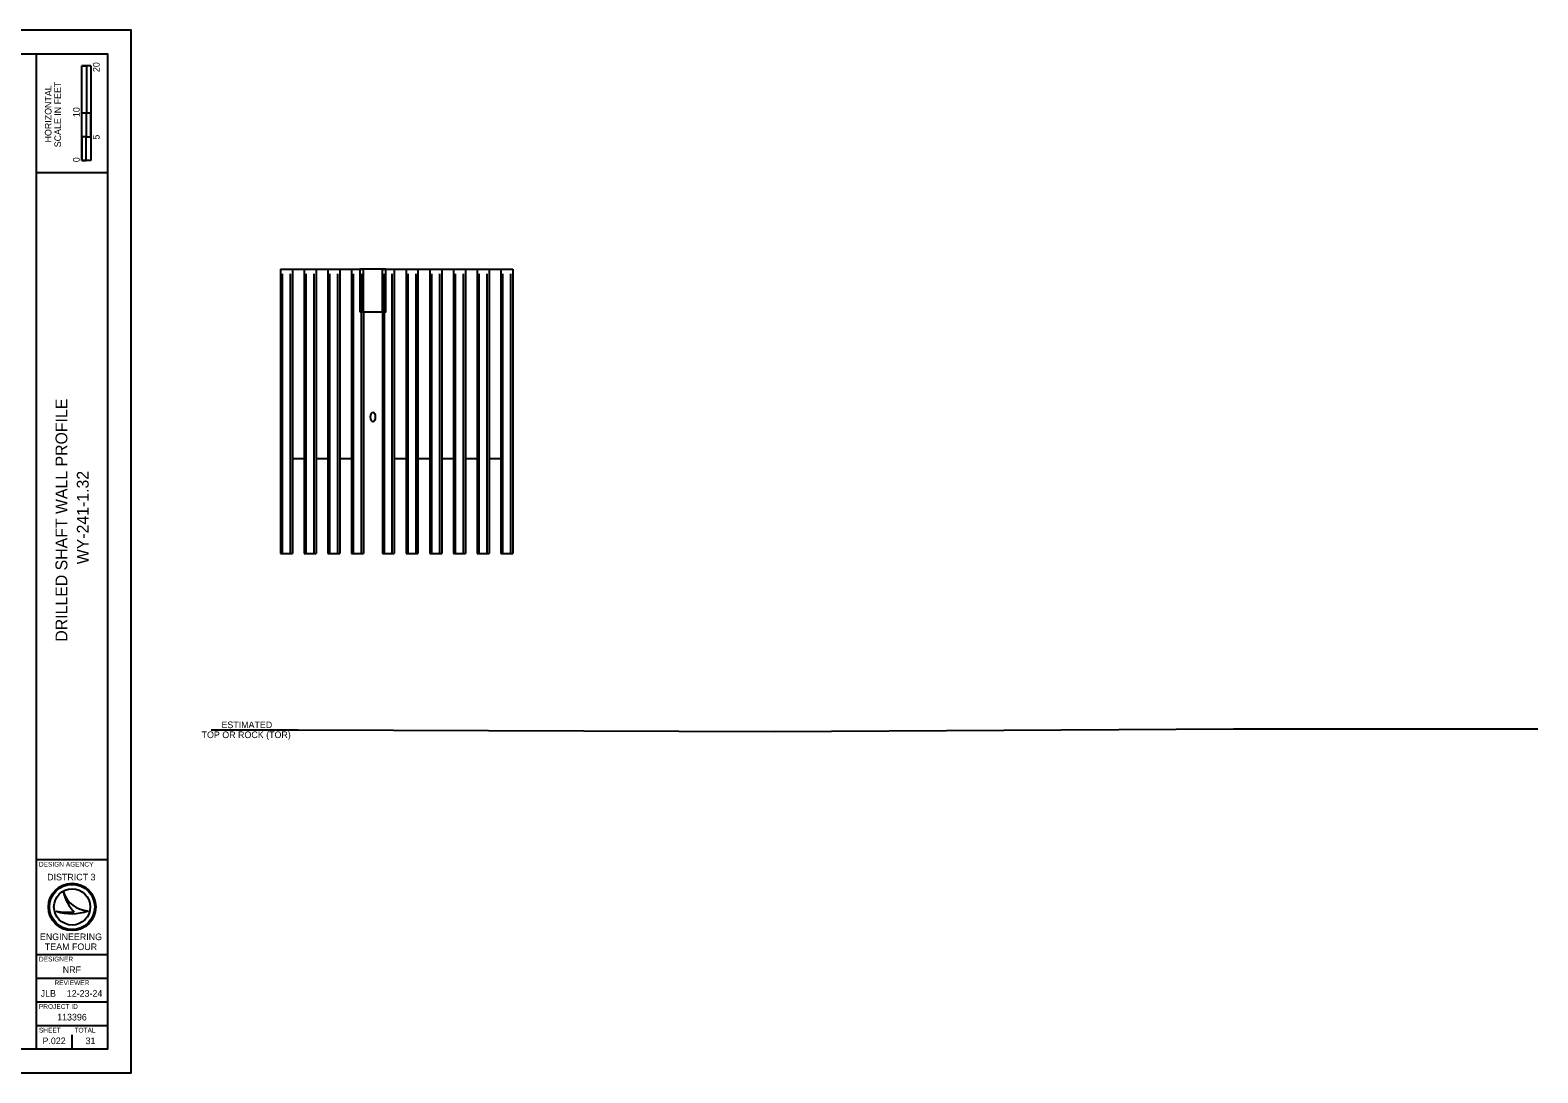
# Model space of a CAD drawing. Extents: x -276 to 637, y 1 to 221.
# Drawn here: x 319.2 to 637.4, y 0.6 to 220.6 of the extents above; entities that cross this region are included whole.
import ezdxf

# ---------------------------------------------------------------- set-up
doc = ezdxf.new("R2010")
doc.units = 0
for name, color, linetype in [('BR_P_Beam_Reinforcing', 7, 'Continuous'), ('DR_X_Culvert', 7, 'Continuous'), ('RD_P_Wall', 7, 'Continuous'), ('RD_X_Bedrock', 7, 'Continuous'), ('SH_Border', 7, 'Continuous'), ('SH_Cut_Line', 7, 'Continuous'), ('SH_Data', 7, 'Continuous')]:
    doc.layers.add(name, color=color, linetype=linetype)

msp = doc.modelspace()

# ---------------------------------------------------------------- linework, layer by layer
at = {"layer": 'BR_P_Beam_Reinforcing'}
for p, q in [((372.51, 110.18), (372.51, 169.18)), ((374.18, 110.18), (374.18, 169.18)), ((377.51, 110.18), (377.51, 169.18)), ((379.18, 110.18), (379.18, 169.18)), ((382.51, 110.18), (382.51, 169.18)), ((384.18, 110.18), (384.18, 169.18)), ((387.51, 110.18), (387.51, 169.18)), ((389.18, 161.18), (389.18, 169.18)), ((394.01, 161.18), (394.01, 169.18)), ((395.68, 110.18), (395.68, 169.18)), ((399.01, 110.18), (399.01, 169.18)), ((400.68, 110.18), (400.68, 169.18)), ((404.03, 110.18), (404.03, 169.18)), ((405.7, 110.18), (405.7, 169.18)), ((409.03, 110.18), (409.03, 169.18)), ((410.7, 110.18), (410.7, 169.18)), ((414.03, 110.18), (414.03, 169.18)), ((415.7, 110.18), (415.7, 169.18)), ((419.03, 110.18), (419.03, 169.18)), ((420.7, 110.18), (420.7, 169.18)), ((389.18, 110.18), (389.18, 161.18)), ((394.01, 110.18), (394.01, 161.18))]:
    msp.add_line(p, q, dxfattribs=at)
at = {"layer": 'DR_X_Culvert'}
msp.add_ellipse((391.59, 138.98), major_axis=(0, 1), ratio=0.5, dxfattribs=at)
at = {"layer": 'RD_P_Wall'}
for p, q in [((372.09, 170.18), (372.09, 110.18)), ((372.09, 170.18), (374.59, 170.18)), ((374.59, 170.18), (374.59, 130.18)), ((374.59, 170.18), (374.59, 110.18)), ((377.09, 170.18), (377.09, 110.18)), ((377.09, 170.18), (379.59, 170.18)), ((379.59, 170.18), (379.59, 110.18)), ((379.59, 170.18), (379.59, 130.18)), ((382.09, 170.18), (382.09, 110.18)), ((382.09, 170.18), (384.59, 170.18)), ((384.59, 170.18), (384.59, 110.18)), ((384.59, 170.18), (384.59, 130.18)), ((387.09, 170.18), (387.09, 110.18)), ((387.09, 170.18), (389.59, 170.18)), ((389.59, 161.18), (389.59, 170.18)), ((393.59, 170.18), (396.09, 170.18)), ((393.59, 161.18), (393.59, 170.18)), ((396.09, 170.18), (396.09, 110.18)), ((396.09, 170.18), (396.09, 130.18)), ((398.59, 170.18), (398.59, 110.18)), ((398.59, 170.18), (401.09, 170.18)), ((401.09, 170.18), (401.09, 110.18)), ((401.09, 170.18), (401.09, 130.18)), ((403.61, 170.18), (403.61, 110.18)), ((403.61, 170.18), (406.11, 170.18)), ((406.11, 170.18), (406.11, 110.18)), ((406.11, 170.18), (406.11, 130.18)), ((408.61, 170.18), (408.61, 110.18)), ((408.61, 170.18), (411.11, 170.18)), ((411.11, 170.18), (411.11, 110.18)), ((411.11, 170.18), (411.11, 130.18)), ((413.61, 170.18), (413.61, 110.18)), ((413.61, 170.18), (416.11, 170.18)), ((416.11, 170.18), (416.11, 110.18)), ((416.11, 170.18), (416.11, 130.18)), ((418.61, 170.18), (418.61, 110.18)), ((418.61, 170.18), (421.11, 170.18)), ((421.11, 170.18), (421.11, 110.18)), ((389.59, 161.18), (389.59, 110.18)), ((393.59, 161.18), (393.59, 110.18)), ((372.09, 110.18), (374.59, 110.18)), ((377.09, 110.18), (379.59, 110.18)), ((382.09, 110.18), (384.59, 110.18)), ((387.09, 110.18), (389.59, 110.18)), ((393.59, 110.18), (396.09, 110.18)), ((398.59, 110.18), (401.09, 110.18)), ((403.61, 110.18), (406.11, 110.18)), ((408.61, 110.18), (411.11, 110.18)), ((413.61, 110.18), (416.11, 110.18)), ((418.61, 110.18), (421.11, 110.18))]:
    msp.add_line(p, q, dxfattribs=at)
for points in [[(374.59, 170.18), (377.09, 170.18), (377.09, 130.18), (374.59, 130.18)], [(379.59, 170.18), (382.09, 170.18), (382.09, 130.18), (379.59, 130.18)], [(384.59, 170.18), (387.09, 170.18), (387.09, 130.18), (384.59, 130.18)], [(396.09, 170.18), (398.59, 170.18), (398.59, 130.18), (396.09, 130.18)], [(401.09, 170.18), (403.59, 170.18), (403.59, 130.18), (401.09, 130.18)], [(406.11, 170.18), (408.61, 170.18), (408.61, 130.18), (406.11, 130.18)], [(411.11, 170.18), (413.61, 170.18), (413.61, 130.18), (411.11, 130.18)], [(416.11, 170.18), (418.61, 170.18), (418.61, 130.18), (416.11, 130.18)]]:
    msp.add_lwpolyline(points, dxfattribs=at)
msp.add_lwpolyline([(388.84, 161.18), (394.34, 161.18), (394.34, 170.18), (388.84, 170.18)], close=True, dxfattribs=at)
at = {"layer": 'RD_X_Bedrock'}
msp.add_lwpolyline([(357.44, 73), (375.81, 73), (476.27, 72.6), (573.19, 73.2), (637.44, 73.2)], dxfattribs=at)
at = {"layer": 'SH_Border'}
for p, q in [((320.6, 5.6), (320.6, 215.6)), ((320.6, 190.6), (335.6, 190.6)), ((320.6, 45.6), (335.6, 45.6)), ((320.6, 25.6), (335.6, 25.6)), ((320.6, 20.6), (335.6, 20.6)), ((320.6, 15.6), (335.6, 15.6)), ((320.6, 10.6), (335.6, 10.6))]:
    msp.add_line(p, q, dxfattribs=at)
msp.add_lwpolyline([(15.6, 215.6), (335.6, 215.6), (335.6, 5.6), (15.6, 5.6)], close=True, dxfattribs=at)
at = {"layer": 'SH_Cut_Line'}
msp.add_lwpolyline([(0.6, 0.6), (340.6, 0.6), (340.6, 220.6), (0.6, 220.6)], close=True, dxfattribs=at)
at = {"layer": 'SH_Data'}
for p, q in [((330.17, 193.1), (330.17, 213.1)), ((332.04, 213.1), (330.17, 213.1)), ((330.17, 203.1), (330.17, 213.1)), ((330.17, 213.1), (331.1, 213.1)), ((331.1, 213.1), (331.11, 213.1)), ((331.11, 213.1), (331.11, 203.1)), ((332.04, 213.1), (332.04, 193.1)), ((331.11, 203.1), (330.17, 203.1)), ((332.03, 203.1), (331.1, 203.1)), ((331.1, 203.1), (331.1, 198.1)), ((332.03, 198.1), (332.03, 203.1)), ((331.1, 198.1), (330.17, 198.1)), ((330.17, 198.1), (330.17, 193.1)), ((331.1, 193.1), (331.1, 198.1)), ((331.1, 198.1), (332.03, 198.1)), ((332.04, 193.1), (330.17, 193.1)), ((330.17, 193.1), (331.1, 193.1)), ((326.27, 38.7), (326.27, 38.7)), ((328.1, 35.6), (328.1, 35.6)), ((324.77, 34.7), (324.77, 34.7)), ((331.47, 34.79), (331.47, 34.79)), ((324.35, 7.35), (324.35, 7.35)), ((328.1, 5.6), (328.1, 8.6))]:
    msp.add_line(p, q, dxfattribs=at)
for radius in [5, 4.77, 4.77, 3.82]:
    msp.add_circle((328.1, 35.6), radius, dxfattribs=at)
for centre, radius, start, end in [((331.76, 40.58), 5.8, 198.9257, 198.9319), ((334.07, 40.3), 7.96, 191.6379, 191.6421), ((331.76, 40.58), 5.8, 198.9319, 267.1657), ((334.07, 40.3), 7.96, 191.6421, 226.0947), ((327.99, 44.3), 10.13, 251.4576, 290.0832), ((327.08, 47.14), 12.66, 259.4964, 259.4995), ((327.99, 44.3), 10.13, 251.4527, 251.4576), ((327.08, 47.14), 12.66, 259.4995, 276.6672)]:
    msp.add_arc(centre, radius, start, end, dxfattribs=at)

# ---------------------------------------------------------------- texts
for s, height, p in [('20', 1.4, (333.9, 211.76)), ('HORIZONTAL', 1.4, (323.75, 196.9)), ('SCALE IN FEET', 1.4, (325.77, 195.89)), ('10', 1.4, (329.7, 202.26)), ('5', 1.4, (333.9, 197.5)), ('0', 1.4, (329.7, 192.74)), ('DRILLED SHAFT WALL PROFILE', 2.5, (327.1, 91.57)), ('WY-241-1.32', 2.5, (331.6, 107.91))]:
    msp.add_text(s, height=height, rotation=90, dxfattribs=at).set_placement(p)
for s, height, p in [('ESTIMATED ', 1.4, (359.62, 73.33)), ('TOP OR ROCK (TOR)', 1.4, (355.43, 71.23)), ('DESIGN AGENCY', 1, (321.1, 44.1)), ('DISTRICT 3', 1.4, (322.84, 41.2)), ('ENGINEERING', 1.4, (321.31, 28.6)), ('TEAM FOUR', 1.4, (322.35, 26.5)), ('DESIGNER', 1, (321.1, 24.1)), ('NRF', 1.4, (326.13, 21.65)), ('REVIEWER', 1, (324.38, 19.1)), ('JLB', 1.4, (321.47, 16.65)), ('12-23-24', 1.4, (326.98, 16.65)), ('PROJECT ID', 1, (321.1, 14.1)), ('113396', 1.4, (324.95, 11.65)), ('SHEET', 1, (321.1, 9.1)), ('TOTAL', 1, (328.6, 9.1)), ('P.022', 1.4, (321.85, 6.65)), ('31', 1.4, (330.94, 6.65))]:
    msp.add_text(s, height=height, dxfattribs=at).set_placement(p)

doc.saveas('drawing.dxf')
